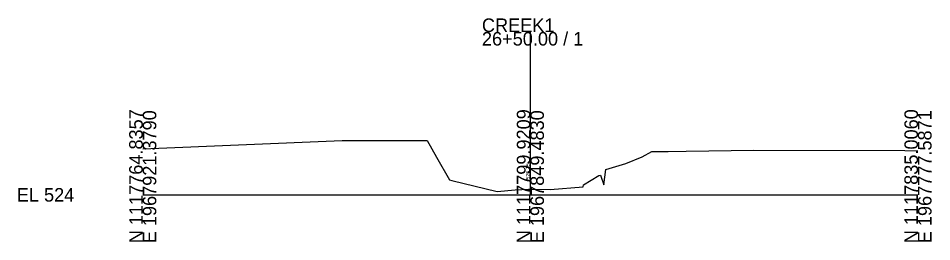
# Model space of a CAD drawing. Extents: x -26 to 163, y -10 to 10052.
# Drawn here: x -25.7 to 162.8, y 5990.3 to 6036.5 of the extents above; entities that cross this region are included whole.
import ezdxf

# ---------------------------------------------------------------- set-up
doc = ezdxf.new("R2010")
doc.units = 0
for name, color, linetype in [('RD_GPK_XS_Cell', 7, 'Continuous'), ('RD_XS_ExGround', 7, 'Continuous'), ('RD_XS_TX_Elev_EX', 7, 'Continuous')]:
    doc.layers.add(name, color=color, linetype=linetype)

msp = doc.modelspace()

# ---------------------------------------------------------------- linework, layer by layer
at = {"layer": 'RD_GPK_XS_Cell'}
for p, q in [((80, 6000), (80, 6033.65)), ((0, 6000), (80, 6000)), ((80, 6000), (160, 6000))]:
    msp.add_line(p, q, dxfattribs=at)
at = {"layer": 'RD_XS_ExGround'}
for p, q in [((0, 6009.5), (41.17, 6011.22)), ((41.17, 6011.22), (42.02, 6011.22)), ((42.02, 6011.22), (43.02, 6011.22)), ((43.02, 6011.22), (58.67, 6011.2)), ((58.67, 6011.2), (60.61, 6007.82)), ((103.09, 6007.83), (105.05, 6008.96)), ((105.05, 6008.96), (108.41, 6008.98)), ((108.41, 6008.98), (112.19, 6009.05)), ((112.19, 6009.05), (126.15, 6009.22)), ((126.15, 6009.22), (157.28, 6009.13)), ((157.28, 6009.13), (160, 6009.12)), ((60.61, 6007.82), (63.32, 6003.12)), ((99.69, 6006.47), (103.09, 6007.83)), ((95.14, 6002.06), (95.55, 6005.27)), ((95.55, 6005.27), (99.69, 6006.47)), ((63.32, 6003.12), (63.82, 6002.99)), ((63.82, 6002.99), (73.13, 6000.66)), ((90.97, 6002.1), (94.16, 6004.01)), ((94.16, 6004.01), (94.48, 6004.05)), ((94.48, 6004.05), (95.14, 6002.06)), ((73.13, 6000.66), (76.84, 6001.05)), ((76.84, 6001.05), (79.63, 6001.16)), ((79.63, 6001.16), (80, 6001.15)), ((80, 6001.15), (84.1, 6001.13)), ((84.1, 6001.13), (90.88, 6001.67)), ((90.88, 6001.67), (90.97, 6002.1))]:
    msp.add_line(p, q, dxfattribs=at)

# ---------------------------------------------------------------- texts
at = {"layer": 'RD_GPK_XS_Cell'}
for s, p in [('CREEK1', (70, 6033.65)), ('26+50.00 / 1', (70, 6030.85)), ('EL 524', (-26, 5998.6))]:
    msp.add_text(s, height=2.8, dxfattribs=at).set_placement(p)
for s, p in [('N 1117764.8357', (0, 5990)), ('E 1967921.3790', (2.8, 5990)), ('N 1117799.9209', (80, 5990)), ('E 1967849.4830', (82.8, 5990)), ('N 1117835.0060', (160, 5990)), ('E 1967777.5871', (162.8, 5990))]:
    msp.add_text(s, height=2.8, rotation=90, dxfattribs=at).set_placement(p)
at = {"layer": 'RD_XS_TX_Elev_EX'}
msp.add_text('525.15', height=0.8, rotation=90, dxfattribs=at).set_placement((79.9, 6003.15))

doc.saveas('drawing.dxf')
